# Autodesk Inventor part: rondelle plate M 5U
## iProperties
Author: chr
Created: 2001-06
Part Number: rondelle plate M 5U
Material: Par défaut
Document SubType Name: Modélisation
Designer: chr
Control State: 0
Master: False
Checked Out: False
PropertySet Name: Design Tracking Control
Shininess: 21.0
PropertySet Name: _Private Model Information
Length Units: 11269
Angle Units: 11286
Time Units: 11279
Mass Units: 11290
Length Display Precision: 3
Angle Display Precision: 2
Compacted: False
Density: 0.0
Volumn: 0.0
Area: 0.0
PropertySet Name: Model Information
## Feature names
1. Extrusion1
